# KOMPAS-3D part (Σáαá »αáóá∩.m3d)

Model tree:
1. Эскиз:1
2. Операция выдавливания:1
     Расстояние 1 = 1; Расстояние 2 = 6
3. Скругление:1
     Радиус = 5
4. Эскиз:2
5. Операция выдавливания:2
     Расстояние 1 = 1; Расстояние 2 = 2
6. Эскиз:3
7. Вырезать элемент выдавливания:1
     Расстояние 1 = 0.1
8. Плоскость, касательная в точке:1
9. Эскиз:4
10. Операция выдавливания:3
     Расстояние 1 = 1; Расстояние 2 = 2
11. Эскиз:5
12. Вырезать элемент выдавливания:2
     Расстояние 1 = 8
13. Эскиз:6
14. Операция выдавливания:4
     Расстояние 1 = 0.7; Расстояние 2 = 2
15. Эскиз:7
16. Операция выдавливания:5
     Расстояние 1 = 0.7; Расстояние 2 = 1
17. Эскиз:9
18. Вырезать элемент выдавливания:3
     Расстояние 1 = 3.08889
19. Скругление:3
     Радиус = 0.2
20. Эскиз:10
21. Операция выдавливания:6
     Расстояние 1 = 0.8; Расстояние 2 = 1
22. Эскиз:11
23. Операция выдавливания:7
     Расстояние 1 = 1.8; Расстояние 2 = 1
24. Эскиз:12
25. Операция выдавливания:8
     Расстояние 1 = 1; Расстояние 2 = 1
26. Эскиз:13
27. Операция выдавливания:9
     Расстояние 1 = 0.1; Расстояние 2 = 1.3
28. Эскиз:14
29. Операция выдавливания:10
     Расстояние 1 = 0.2; Расстояние 2 = 1.3
30. Эскиз:15
31. Операция выдавливания:11
     Расстояние 1 = 0.1; Расстояние 2 = 1.3
32. Скругление:4
     Радиус = 0.1
33. Массив по концентрической сетке:1  (with: Операция выдавливания:11, Скругление:4)  (labels: Экземпляр ( 1, 1 ); Экземпляр ( 1, 2 ); Экземпляр ( 1, 3 ); Экземпляр ( 1, 4 ))
     N 2 = 5; Шаг 2 = 360; Номер 2 = 1
34. Массив по концентрической сетке:2  (with: Операция выдавливания:3, Вырезать элемент выдавливания:2, Операция выдавливания:4, Операция выдавливания:5, Вырезать элемент выдавливания:3, Скругление:3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)  (labels: Экземпляр ( 1, 1 ); Экземпляр ( 1, 2 ); Экземпляр ( 1, 3 ); Экземпляр ( 1, 4 ))
     N 2 = 4; Шаг 2 = 360; Номер 2 = 1
35. Эскиз:16
36. Операция выдавливания:12
     Расстояние 1 = 0.1; Расстояние 2 = 5
37. Скругление:6
     Радиус = 0.3
38. Эскиз:17
39. Вырезать элемент выдавливания:4
     Расстояние 1 = 2

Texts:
  stalker61
  Сплав АЛ8  ГОСТ 1583-93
